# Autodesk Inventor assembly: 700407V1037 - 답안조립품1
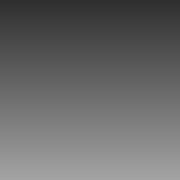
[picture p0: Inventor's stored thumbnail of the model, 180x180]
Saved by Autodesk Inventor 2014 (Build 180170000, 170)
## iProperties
Created: 2020-04
Part Number: 700407V1037 - 답안조립품1
Document SubType Name: Assembly
Designer: kh
Author: kh
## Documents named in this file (1)
- C:\Users\kh\Desktop\700407V1037\700407V1037 - 답안조립품1.iam
